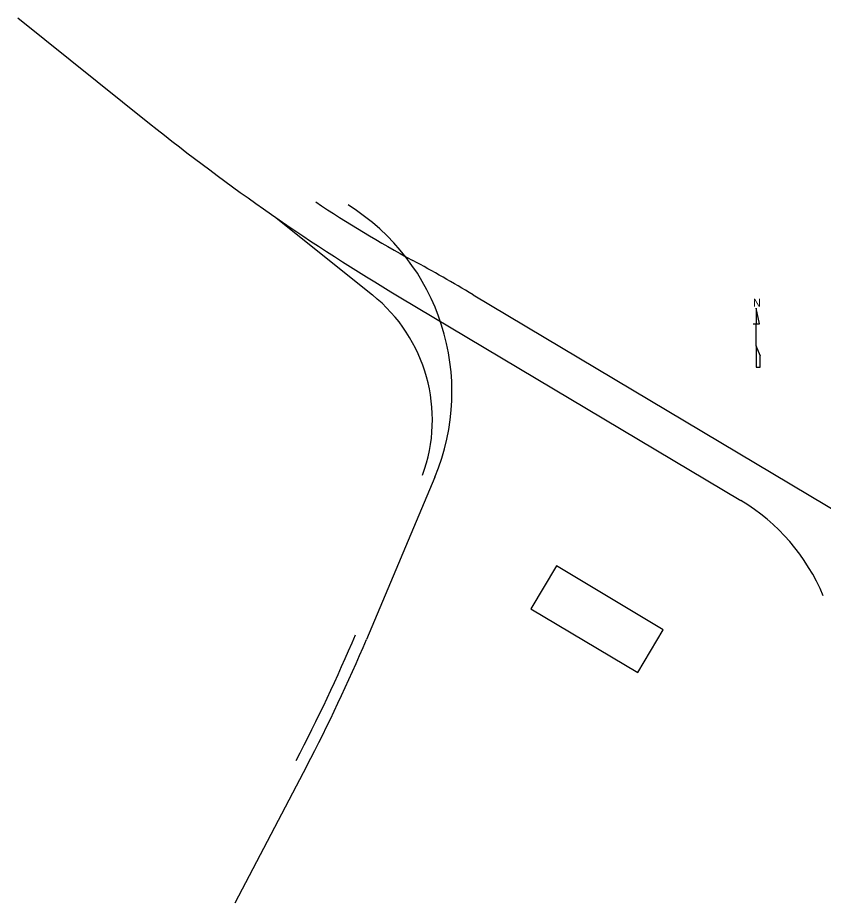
# Model space of a CAD drawing. Extents: x 2344331 to 2350764, y 366700 to 371189.
# Drawn here: x 2344331 to 2348357, y 366762 to 371189 of the extents above; entities that cross this region are included whole.
import ezdxf

# ---------------------------------------------------------------- set-up
doc = ezdxf.new("R2010")
doc.units = 0
for name, color, linetype in [('Default', 7, 'Continuous'), ('RD_EX_Misc', 7, 'Continuous'), ('RD_HC_Cl', 7, 'Continuous'), ('RD_PD_Final_LnLine', 7, 'Continuous'), ('TR PM UNASSIGNED 3', 7, 'Continuous')]:
    doc.layers.add(name, color=color, linetype=linetype)

# ---------------------------------------------------------------- blocks, each defined once
blk = doc.blocks.new('NA')
at = {"layer": 'RD_EX_Misc'}
for p, q in [((7.9, 31.1), (0.1, 70.3)), ((0.1, 70.3), (0.1, 70.3)), ((0.1, 70.3), (0.1, 31.1)), ((-7.8, 31.1), (0.1, 31.1)), ((0.1, -23.3), (0.1, 31.1)), ((0.1, 31.1), (7.9, 31.1)), ((7.9, 31.1), (7.9, 31.5)), ((9.9, -47.3), (0.1, -23.3)), ((0.1, -23.3), (0.1, -76.7)), ((9.9, -76.7), (9.9, -47.1)), ((9.9, -47.1), (9.9, -47.3)), ((0.1, -76.7), (9.9, -76.7))]:
    blk.add_line(p, q, dxfattribs=at)
blk.add_text('N', height=20, dxfattribs=at).set_placement((-7.8, 74))

msp = doc.modelspace()

# ---------------------------------------------------------------- linework, layer by layer
at = {"layer": 'RD_HC_Cl'}
for p, q in [((2345614.6, 370194.7), (2346103.4, 369803.5)), ((2345614.6, 370194.7), (2346103.4, 369803.5)), ((2345614.6, 370194.7), (2346103.4, 369803.5)), ((2345614.6, 370194.7), (2346103.4, 369803.5)), ((2346606.5, 369804.5), (2348463.1, 368696.8)), ((2346606.5, 369804.5), (2348463.1, 368696.8)), ((2346606.5, 369804.5), (2348463.1, 368696.8)), ((2346606.5, 369804.5), (2348463.1, 368696.8)), ((2346414.9, 368892.2), (2346073.6, 368081.3)), ((2346414.9, 368892.2), (2346073.6, 368081.3)), ((2346414.9, 368892.2), (2346073.6, 368081.3)), ((2346414.9, 368892.2), (2346073.6, 368081.3)), ((2345775.2, 367448.5), (2345415, 366761.9)), ((2345775.2, 367448.5), (2345415, 366761.9)), ((2345775.2, 367448.5), (2345415, 366761.9)), ((2345775.2, 367448.5), (2345415, 366761.9))]:
    msp.add_line(p, q, dxfattribs=at)
for centre, radius, start, end in [((2349158.4, 375253.9), 6000, 236.19528, 241.60251), ((2349158.4, 375253.9), 6000, 236.19528, 241.60251), ((2349158.4, 375253.9), 6000, 236.19528, 241.60251), ((2349158.4, 375253.9), 6000, 236.19528, 241.60251), ((2345401.1, 369318.9), 1100, 337.175, 58.1352), ((2345401.1, 369318.9), 1100, 337.175, 58.1352), ((2345401.1, 369318.9), 1100, 337.175, 58.1352), ((2345401.1, 369318.9), 1100, 337.175, 58.1352), ((2342405.1, 362762.6), 8200, 59.17851, 61.60251), ((2342405.1, 362762.6), 8200, 59.17851, 61.60251), ((2342405.1, 362762.6), 8200, 59.17851, 61.60251), ((2342405.1, 362762.6), 8200, 59.17851, 61.60251), ((2345603.4, 369178.9), 800, 339.7746, 51.3248), ((2345603.4, 369178.9), 800, 339.7746, 51.3248), ((2345603.4, 369178.9), 800, 339.7746, 51.3248), ((2345603.4, 369178.9), 800, 339.7746, 51.3248), ((2338460.5, 371285.5), 8200, 332.32074, 337.175), ((2338460.5, 371285.5), 8200, 332.32074, 337.175), ((2338460.5, 371285.5), 8200, 332.32074, 337.175), ((2338460.5, 371285.5), 8200, 332.32074, 337.175), ((2338460.5, 371285.5), 8260, 332.32074, 337.175), ((2338460.5, 371285.5), 8260, 332.32074, 337.175), ((2338460.5, 371285.5), 8260, 332.32074, 337.175), ((2338460.5, 371285.5), 8260, 332.32074, 337.175)]:
    msp.add_arc(centre, radius, start, end, dxfattribs=at)
at = {"layer": 'RD_PD_Final_LnLine'}
for p, q in [((2344330.6, 371189.3), (2344989.7, 370660.6)), ((2344330.6, 371189.3), (2344989.7, 370660.6)), ((2344330.6, 371189.3), (2344989.7, 370660.6)), ((2344330.6, 371189.3), (2344989.7, 370660.6)), ((2346236.7, 369794.6), (2347945.2, 368775.3)), ((2346236.7, 369794.6), (2347945.2, 368775.3)), ((2346236.7, 369794.6), (2347945.2, 368775.3)), ((2346236.7, 369794.6), (2347945.2, 368775.3))]:
    msp.add_line(p, q, dxfattribs=at)
for centre, radius, start, end in [((2351872.8, 379241), 11000, 231.26372, 239.17851), ((2351872.8, 379241), 11000, 231.26372, 239.17851), ((2351872.8, 379241), 11000, 231.26372, 239.17851), ((2351872.8, 379241), 11000, 231.26372, 239.17851), ((2347432.8, 367916.5), 1000, 22.4559, 59.1785), ((2347432.8, 367916.5), 1000, 22.4559, 59.1785), ((2347432.8, 367916.5), 1000, 22.4559, 59.1785), ((2347432.8, 367916.5), 1000, 22.4559, 59.1785)]:
    msp.add_arc(centre, radius, start, end, dxfattribs=at)
at = {"layer": 'TR PM UNASSIGNED 3'}
msp.add_lwpolyline([(2346894.8, 368234), (2347429.3, 367915.1), (2347557.2, 368129.5), (2347022.8, 368448.4)], close=True, dxfattribs=at)

# ---------------------------------------------------------------- block references
at = {"layer": 'Default', "xscale": 2, "yscale": 2}
msp.add_blockref('NA', (2348021.8, 369595.9), dxfattribs=at)

doc.saveas('drawing.dxf')
